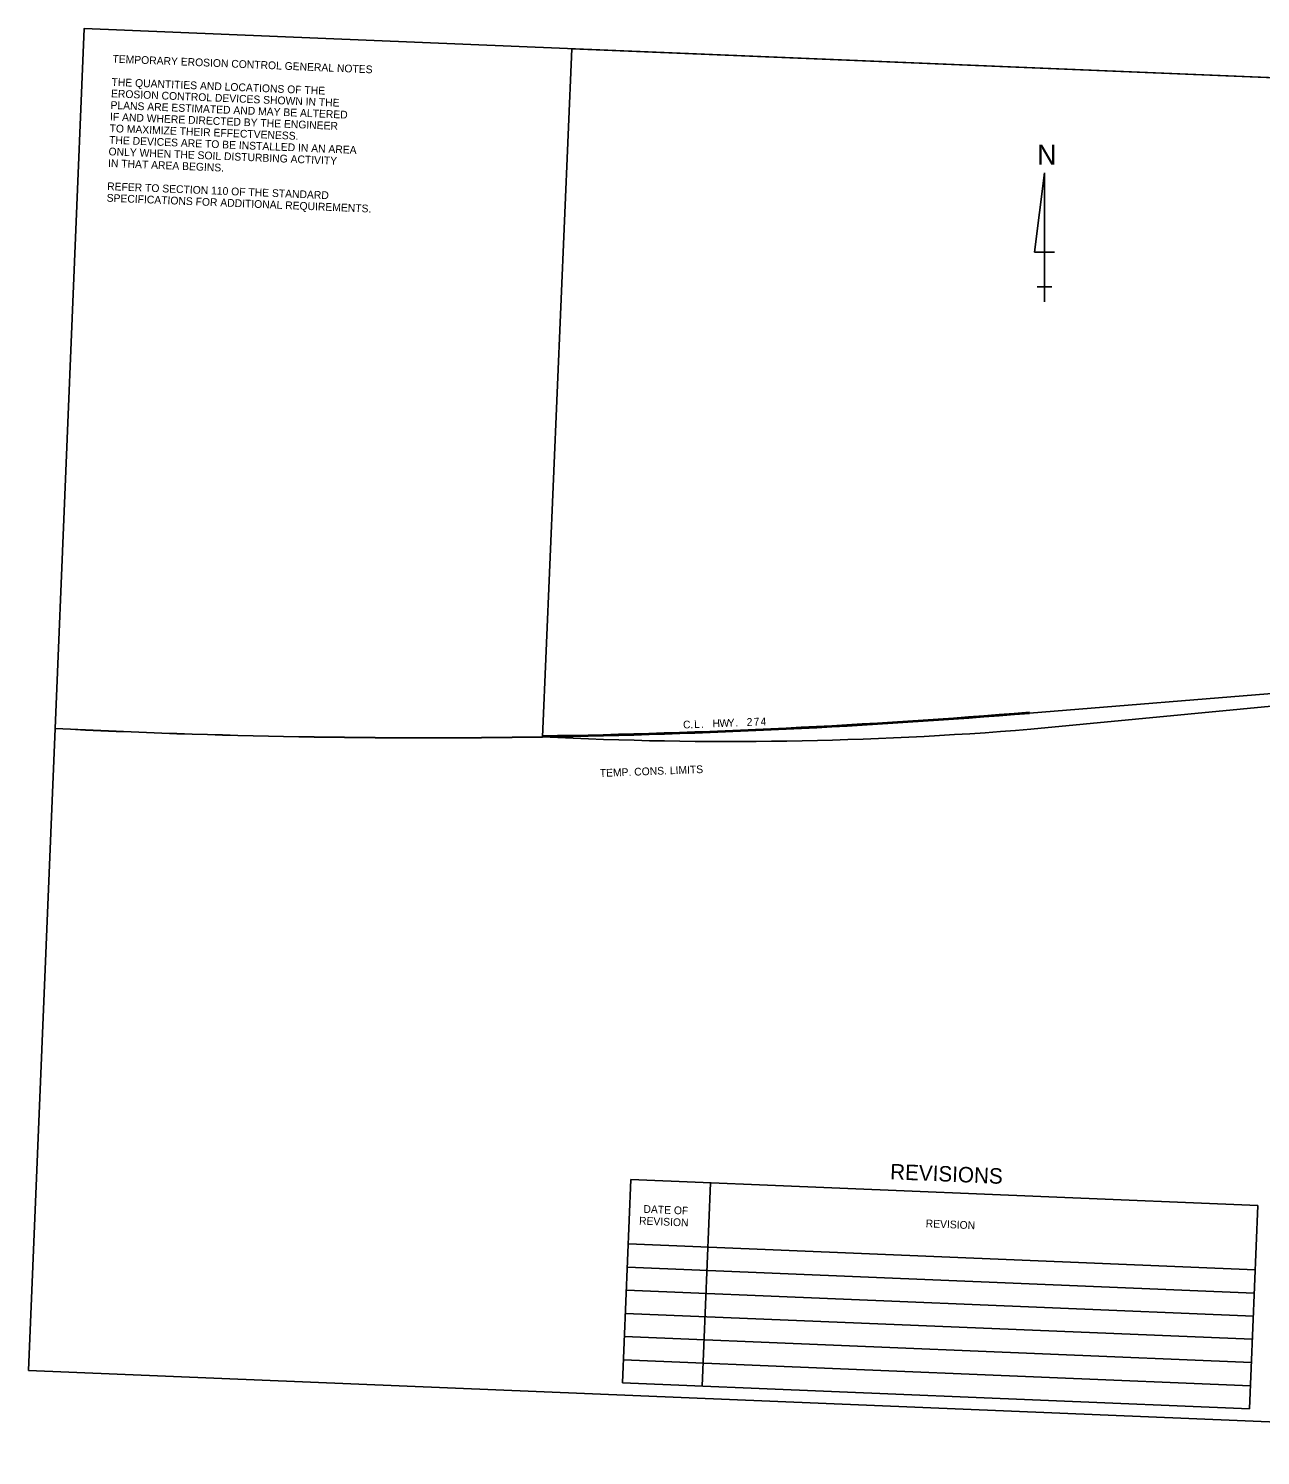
# Model space of a CAD drawing. Extents: x 1141828 to 1143465, y 1657046 to 1658153.
# Drawn here: x 1141828 to 1142784, y 1657046 to 1658153 of the extents above; entities that cross this region are included whole.
import ezdxf

# ---------------------------------------------------------------- set-up
doc = ezdxf.new("R2010")
doc.units = 0
for name, color, linetype in [('R_Annotation', 7, 'Continuous'), ('R_Horz Alg', 7, 'Continuous'), ('R_No Plot', 7, 'Continuous'), ('S_BASELINE', 7, 'Continuous')]:
    doc.layers.add(name, color=color, linetype=linetype)

msp = doc.modelspace()

# ---------------------------------------------------------------- linework, layer by layer
at = {"layer": 'R_Annotation'}
for p, q in [((1142616.3, 1658041), (1142608.6, 1657979.5)), ((1142616.3, 1657941), (1142616.3, 1658041)), ((1142616.3, 1658041), (1142616.3, 1657964.1)), ((1142608.6, 1657979.5), (1142624, 1657979.5)), ((1142616.3, 1657941), (1142616.3, 1657964.1)), ((1142616.3, 1657952.5), (1142610.6, 1657952.5)), ((1142610.6, 1657952.5), (1142622.1, 1657952.5)), ((1142616.3, 1657941), (1142616.3, 1657952.5))]:
    msp.add_line(p, q, dxfattribs=at)
at = {"layer": 'R_Horz Alg'}
msp.add_arc((1142137.7, 1663333), 5729.6, 270.88999, 274.675, dxfattribs=at)
at = {"layer": 'R_No Plot'}
for p, q in [((1143448.8, 1657690.7), (1142604.7, 1657621.7)), ((1143448.8, 1657690.6), (1142604.7, 1657621.6)), ((1143448.8, 1657690.7), (1142605.7, 1657609.2))]:
    msp.add_line(p, q, dxfattribs=at)
for points in [[(1141848.7, 1657609.9), (1141871.2, 1658153), (1143465.2, 1658087.1), (1143448.8, 1657690.7)], [(1142226.9, 1657603.3), (1142249.6, 1658137.4), (1143465.2, 1658087.1), (1143448.8, 1657690.7)], [(1141848.7, 1657609.8), (1141828.1, 1657111.6), (1143422.1, 1657045.7), (1143448.8, 1657690.6)]]:
    msp.add_lwpolyline(points, dxfattribs=at)
for radius, start in [(5730.4, 267.10958), (5730.5, 267.10963)]:
    msp.add_arc((1142137.7, 1663333), radius, start, 274.675, dxfattribs=at)
msp.add_ellipse((1142371.7, 1660471.1), major_axis=(0, 2871.4), ratio=0.999982, start_param=3.091145, end_param=3.223187, dxfattribs=at)
at = {"layer": 'S_BASELINE'}
for p, q in [((1142295.5, 1657259.8), (1142289, 1657101.9)), ((1142295.5, 1657259.8), (1142781.9, 1657239.7)), ((1142357.3, 1657257.3), (1142350.8, 1657099.4)), ((1142781.9, 1657239.7), (1142775.4, 1657081.8)), ((1142293.5, 1657209.8), (1142779.9, 1657189.7)), ((1142292.7, 1657191.9), (1142779.1, 1657171.7)), ((1142292, 1657173.9), (1142778.4, 1657153.8)), ((1142291.2, 1657155.9), (1142777.6, 1657135.8)), ((1142290.5, 1657137.9), (1142776.9, 1657117.8)), ((1142289.8, 1657119.9), (1142776.1, 1657099.8)), ((1142289, 1657101.9), (1142775.4, 1657081.8))]:
    msp.add_line(p, q, dxfattribs=at)

# ---------------------------------------------------------------- texts
at = {"layer": 'R_Annotation'}
for s, rotation, p in [('TEMPORARY EROSION CONTROL GENERAL NOTES', 357.6311, (1141893.1, 1658126.6)), ('THE QUANTITIES AND LOCATIONS OF THE', 357.6311, (1141892.4, 1658108.6)), ('PLANS ARE ESTIMATED AND MAY BE ALTERED ', 357.6311, (1141891.6, 1658090.7)), ('EROSION CONTROL DEVICES SHOWN IN THE ', 357.6311, (1141892, 1658099.7)), ('IF AND WHERE DIRECTED BY THE ENGINEER ', 357.6311, (1141891.2, 1658081.7)), ('TO MAXIMIZE THEIR EFFECTVENESS. ', 357.6311, (1141890.9, 1658072.7)), ('THE DEVICES ARE TO BE INSTALLED IN AN AREA ', 357.6311, (1141890.5, 1658063.7)), ('IN THAT AREA BEGINS.', 357.6311, (1141889.7, 1658045.7)), ('ONLY WHEN THE SOIL DISTURBING ACTIVITY', 357.6311, (1141890.1, 1658054.7)), ('REFER TO SECTION 110 OF THE STANDARD ', 357.6311, (1141889, 1658027.7)), ('SPECIFICATIONS FOR ADDITIONAL REQUIREMENTS.', 357.6311, (1141888.6, 1658018.7)), ('C', 2.0132, (1142336, 1657609.8)), ('.', 2.0699, (1142341.7, 1657610)), ('L', 2.0992, (1142344.6, 1657610.2)), ('.', 2.1531, (1142350, 1657610.3)), ('H', 2.2425, (1142358.9, 1657610.7)), ('W', 2.2964, (1142364.3, 1657610.9)), ('Y', 2.3606, (1142370.7, 1657611.2)), ('.', 2.4183, (1142376.5, 1657611.4)), ('2', 2.5076, (1142385.4, 1657611.8)), ('7', 2.5615, (1142390.8, 1657612)), ('4', 2.6154, (1142396.2, 1657612.2)), ('TEMP. CONS. LIMITS', 2.2033, (1142271.4, 1657572.2))]:
    msp.add_text(s, height=6, rotation=rotation, dxfattribs=at).set_placement(p)
msp.add_text('N', height=15.4, dxfattribs=at).set_placement((1142610.7, 1658047.4))
at = {"layer": 'S_BASELINE'}
for s, height, p in [('REVISIONS', 12, (1142496.4, 1657260)), ('DATE OF', 6, (1142305.1, 1657234)), ('REVISION', 6, (1142301.7, 1657224.9)), ('REVISION', 6, (1142524.1, 1657222.8))]:
    msp.add_text(s, height=height, rotation=357.6311, dxfattribs=at).set_placement(p)

doc.saveas('drawing.dxf')
